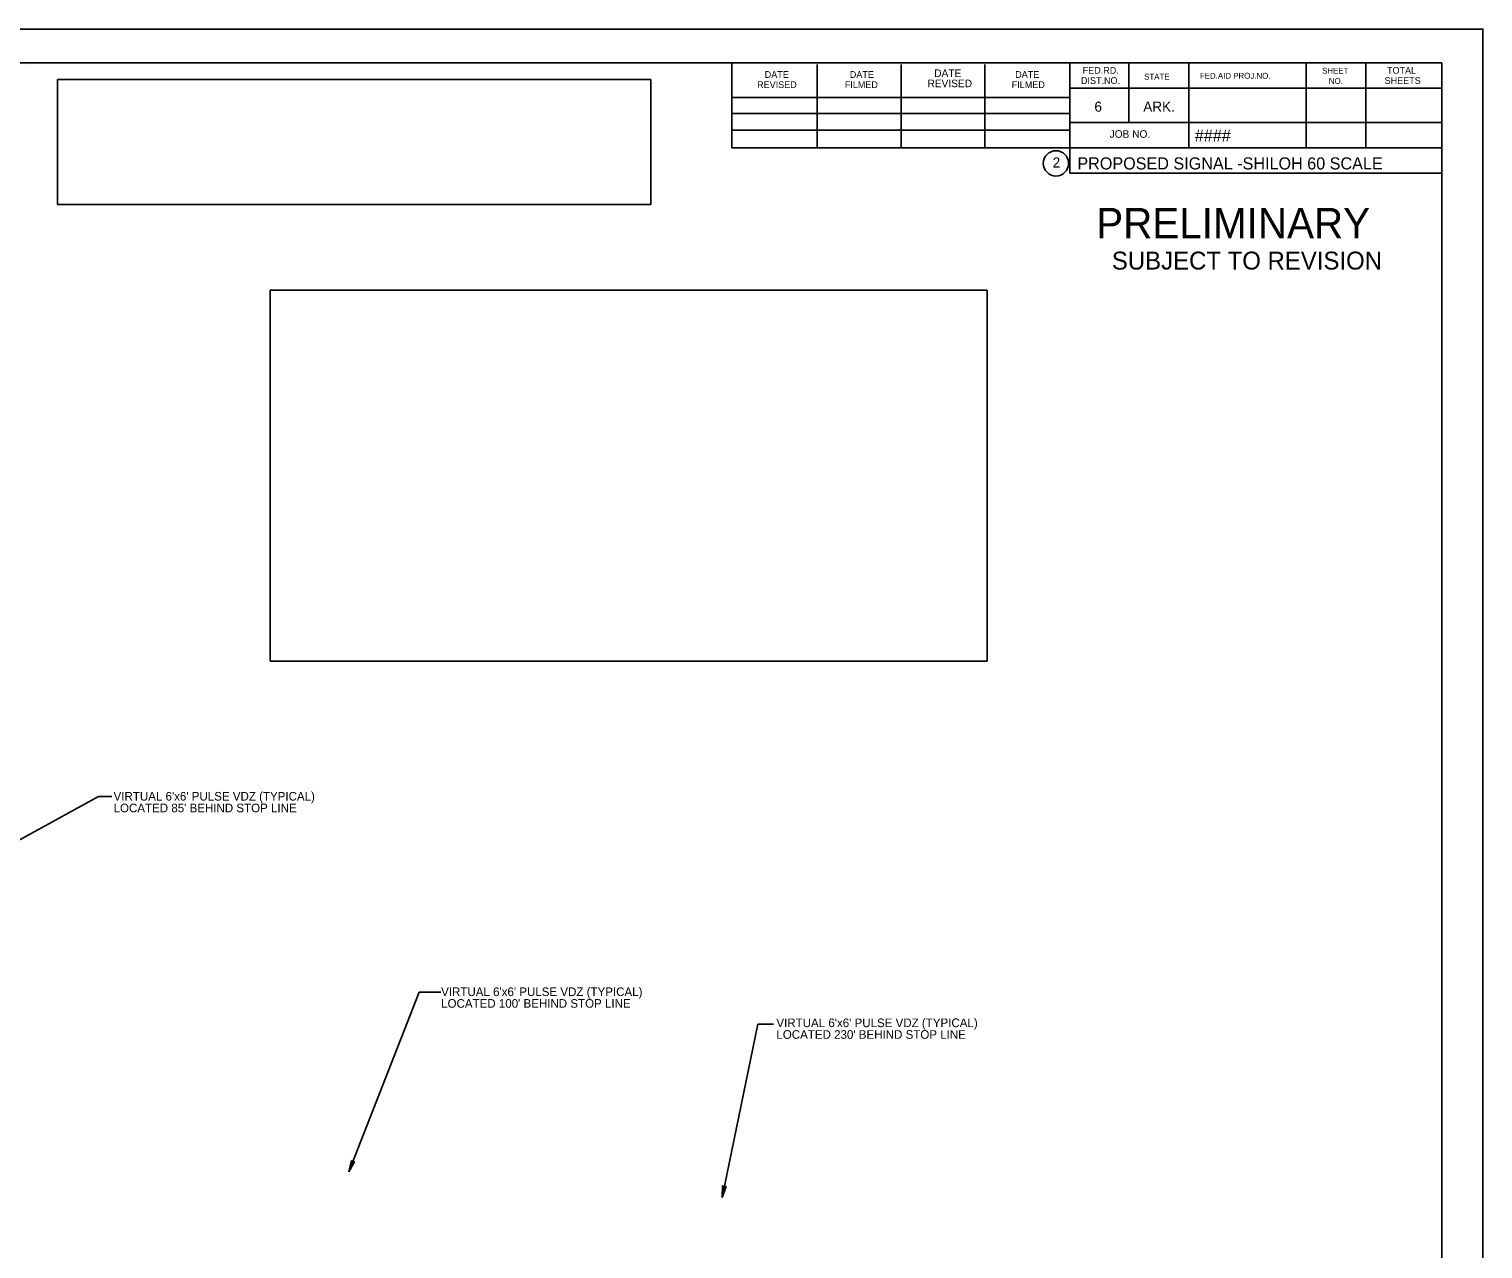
# Model space of a CAD drawing. Extents: x 660063 to 664816, y 641756 to 643817.
# Drawn here: x 661905 to 662411, y 642465 to 642889 of the extents above; entities that cross this region are included whole.
import ezdxf

# ---------------------------------------------------------------- set-up
doc = ezdxf.new("R2010")
doc.units = 0
for name, color, linetype in [('R_Border', 7, 'Continuous'), ('R_Border Prem', 7, 'Continuous'), ('R_No Plot', 7, 'Continuous'), ('T_Drafting', 7, 'Continuous')]:
    doc.layers.add(name, color=color, linetype=linetype)

msp = doc.modelspace()

# ---------------------------------------------------------------- linework, layer by layer
at = {"layer": 'R_Border'}
for p, q in [((661447.99, 642876.97), (662396.53, 642876.97)), ((661905.55, 642876.19), (661905.55, 642876.19)), ((661905.55, 642876.19), (661905.55, 642876.19)), ((662149.75, 642847.33), (662149.75, 642876.97)), ((662179.33, 642847.33), (662179.33, 642876.37)), ((662208.61, 642847.33), (662208.61, 642876.37)), ((662237.65, 642847.33), (662237.65, 642876.37)), ((662267.23, 642876.97), (662267.23, 642838.57)), ((662287.75, 642876.97), (662287.75, 642856.15)), ((662308.57, 642876.97), (662308.57, 642847.33)), ((662349.31, 642876.97), (662349.31, 642847.33)), ((662370.13, 642876.97), (662370.13, 642847.33)), ((662396.53, 642260.59), (662396.53, 642876.97)), ((662396.53, 642868.15), (662267.23, 642868.15)), ((662396.53, 642868.21), (662396.53, 642868.21)), ((662149.75, 642864.91), (662267.23, 642864.91)), ((662149.75, 642859.33), (662267.23, 642859.33)), ((662396.53, 642856.15), (662267.23, 642856.15)), ((662276.11, 642856.15), (662396.53, 642856.15)), ((662149.75, 642847.33), (662149.75, 642853.51)), ((662149.75, 642853.51), (662267.23, 642853.51)), ((662396.53, 642847.33), (662149.75, 642847.33)), ((662267.23, 642838.57), (662396.53, 642838.57))]:
    msp.add_line(p, q, dxfattribs=at)
msp.add_circle((662262.39, 642841.98), 4.4, dxfattribs=at)
at = {"layer": 'R_No Plot'}
msp.add_line((661410.79, 642888.66), (662410.79, 642888.66), dxfattribs=at)
msp.add_lwpolyline([(661410.77, 642888.66), (662410.79, 642888.66), (662410.79, 642248.64), (661410.77, 642248.64)], close=True, dxfattribs=at)
at = {"layer": 'T_Drafting'}
for p, q in [((661929.59, 642621.84), (661901.56, 642606.48)), ((661934.18, 642621.84), (661929.59, 642621.84)), ((662041.08, 642553.9), (662016.61, 642491.38)), ((662048.59, 642553.9), (662041.08, 642553.9)), ((662158.8, 642542.8), (662146.31, 642482.51)), ((662164.24, 642542.8), (662158.8, 642542.8)), ((662017.51, 642495.32), (662016.61, 642491.38)), ((662018.62, 642494.89), (662016.61, 642491.38)), ((662017.6, 642495.29), (662016.85, 642492)), ((662018.53, 642494.92), (662016.85, 642492)), ((662017.69, 642495.25), (662017.1, 642492.64)), ((662018.44, 642494.96), (662017.1, 642492.64)), ((662017.79, 642495.21), (662017.34, 642493.26)), ((662018.34, 642495), (662017.34, 642493.26)), ((662018.62, 642494.89), (662017.51, 642495.32)), ((662017.88, 642495.18), (662017.59, 642493.9)), ((662018.25, 642495.04), (662017.59, 642493.9)), ((662017.98, 642495.14), (662017.83, 642494.52)), ((662018.15, 642495.07), (662017.83, 642494.52)), ((662146.53, 642486.55), (662146.31, 642482.51)), ((662147.71, 642486.31), (662146.31, 642482.51)), ((662146.63, 642486.53), (662146.44, 642483.17)), ((662147.61, 642486.33), (662146.44, 642483.17)), ((662147.71, 642486.31), (662146.53, 642486.55)), ((662146.73, 642486.51), (662146.58, 642483.84)), ((662147.51, 642486.35), (662146.58, 642483.84)), ((662146.83, 642486.49), (662146.72, 642484.49)), ((662147.41, 642486.37), (662146.72, 642484.49)), ((662146.93, 642486.47), (662146.86, 642485.16)), ((662147.31, 642486.39), (662146.86, 642485.16)), ((662147.03, 642486.45), (662146.99, 642485.81)), ((662147.21, 642486.41), (662146.99, 642485.81))]:
    msp.add_line(p, q, dxfattribs=at)
for points in [[(661915.35, 642827.7), (662121.51, 642827.7), (662121.51, 642871.11), (661915.35, 642871.11)], [(661989.29, 642668.98), (662238.42, 642668.98), (662238.42, 642797.88), (661989.29, 642797.88)]]:
    msp.add_lwpolyline(points, close=True, dxfattribs=at)

# ---------------------------------------------------------------- texts
at = {"layer": 'R_Border'}
for s, height, p in [('DATE', 2.346, (662161.15, 642871.69)), ('DATE', 2.346, (662190.73, 642871.69)), ('REVISED', 2.638, (662217.73, 642868.45)), ('DATE', 2.638, (662220.07, 642871.99)), ('DATE', 2.346, (662248.21, 642871.69)), ('DIST.NO.', 2.346, (662271.07, 642869.59)), ('FED.RD.', 2.346, (662271.67, 642873.13)), ('STATE', 2.052, (662293.03, 642871.09)), ('FED.AID PROJ.NO.', 2.052, (662312.41, 642871.39)), ('SHEET', 2.052, (662354.89, 642873.13)), ('NO.', 2.052, (662357.23, 642869.59)), ('SHEETS', 2.346, (662376.61, 642869.59)), ('TOTAL', 2.346, (662377.45, 642873.13)), ('REVISED', 2.346, (662158.51, 642868.15)), ('FILMED', 2.346, (662188.99, 642868.15)), ('FILMED', 2.346, (662247.01, 642868.15)), ('6', 3.52, (662275.75, 642859.93)), ('ARK.', 3.517, (662292.73, 642859.93)), ('JOB NO.', 2.638, (662281.03, 642850.87)), ('####', 4.2, (662310.66, 642849.55)), ('2', 3.52, (662261.24, 642840.52)), ('PROPOSED SIGNAL -SHILOH 60 SCALE', 4.2, (662269.82, 642839.86))]:
    msp.add_text(s, height=height, rotation=360, dxfattribs=at).set_placement(p)
at = {"layer": 'R_Border Prem'}
for s, height, p in [('PRELIMINARY', 10.5, (662276.38, 642815.96)), ('SUBJECT TO REVISION', 6.2253, (662281.81, 642805.07))]:
    msp.add_text(s, height=height, rotation=360, dxfattribs=at).set_placement(p)
at = {"layer": 'T_Drafting'}
for s, p in [("VIRTUAL 6'x6' PULSE VDZ (TYPICAL)", (661934.83, 642620.47)), ("LOCATED 85' BEHIND STOP LINE", (661934.83, 642616.4)), ("VIRTUAL 6'x6' PULSE VDZ (TYPICAL)", (662048.68, 642552.52)), ("LOCATED 100' BEHIND STOP LINE", (662048.68, 642548.46)), ("VIRTUAL 6'x6' PULSE VDZ (TYPICAL)", (662165.21, 642541.72)), ("LOCATED 230' BEHIND STOP LINE", (662165.21, 642537.66))]:
    msp.add_text(s, height=3, dxfattribs=at).set_placement(p)

doc.saveas('drawing.dxf')
